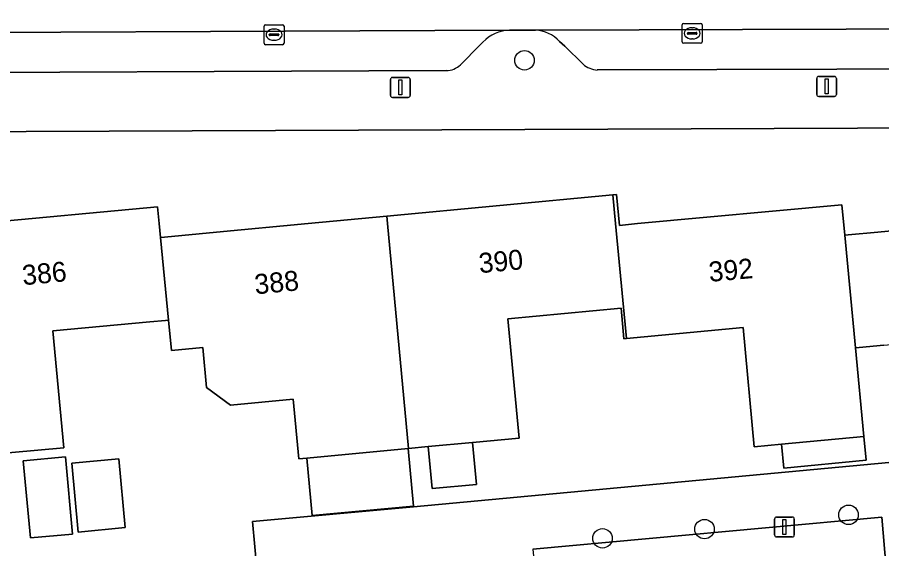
# Model space of a CAD drawing. Extents: x 157793 to 159380, y 380877 to 382313.
# Drawn here: x 158390.06 to 158433.42, y 381233.72 to 381260.34 of the extents above; entities that cross this region are included whole.
import ezdxf

# ---------------------------------------------------------------- set-up
doc = ezdxf.new("R2010")
doc.units = 0
for name, color, linetype in [('IMGEO_Boom', 7, 'Continuous'), ('IMGEO_Erf', 7, 'Continuous'), ('IMGEO_Kolk', 7, 'Continuous'), ('IMGEO_Lichtmast', 7, 'Continuous'), ('IMGEO_Muur', 7, 'Continuous'), ('IMGEO_Pand', 7, 'Continuous'), ('IMGEO_Pand_nummerreeks', 7, 'Continuous'), ('IMGEO_Parkeervlak_open', 7, 'Continuous'), ('IMGEO_Rijbaan_lokaal_gesloten', 7, 'Continuous'), ('IMGEO_Voetpad_open', 7, 'Continuous')]:
    doc.layers.add(name, color=color, linetype=linetype)

msp = doc.modelspace()

# ---------------------------------------------------------------- linework, layer by layer
at = {"layer": 'IMGEO_Boom'}
for centre in [(158415.502, 381258.182), (158431.754, 381235.411), (158424.53, 381234.699), (158419.412, 381234.236)]:
    msp.add_circle(centre, 0.489, dxfattribs=at)
at = {"layer": 'IMGEO_Erf'}
for points in [[(158457.221, 381254.886), (158373.812, 381254.547), (158374.358, 381248.767), (158385.741, 381249.78), (158388.106, 381250), (158397.101, 381250.836), (158397.182, 381250), (158397.249, 381249.305), (158397.445, 381249.323), (158400.053, 381249.568), (158404.644, 381250), (158408.591, 381250.371), (158419.936, 381251.438), (158420.115, 381251.455), (158420.259, 381249.915), (158421.175, 381250), (158431.419, 381250.951), (158431.563, 381249.427), (158431.727, 381249.442), (158433.226, 381249.581), (158437.743, 381250)], [(158433.519, 381243.917), (158432.283, 381243.801), (158432.1, 381243.784), (158432.523, 381239.343), (158432.635, 381238.147), (158428.503, 381237.758), (158428.391, 381238.954), (158427.025, 381238.826), (158426.463, 381244.799), (158420.612, 381244.249), (158420.489, 381244.237), (158420.344, 381245.77), (158414.669, 381245.236), (158415.23, 381239.262), (158412.894, 381239.042), (158413.093, 381236.936), (158410.872, 381236.727), (158410.673, 381238.833), (158409.689, 381238.741), (158409.675, 381238.74), (158409.94, 381235.854), (158404.857, 381235.386), (158404.586, 381238.26), (158404.178, 381238.222), (158403.897, 381241.207), (158400.754, 381240.911), (158399.55, 381241.787), (158399.361, 381243.795), (158397.797, 381243.648), (158397.65, 381245.17), (158397.498, 381245.156), (158396.708, 381245.082), (158391.842, 381244.624), (158392.391, 381238.778), (158388.467, 381238.425)], [(158383.543, 381226.677), (158390.701, 381227.35), (158390.56, 381228.843), (158392.511, 381229.026), (158396.772, 381229.427), (158402.322, 381229.995), (158401.867, 381235.072), (158409.933, 381235.822), (158434.485, 381238.106)]]:
    msp.add_lwpolyline(points, dxfattribs=at)
for points in [[(158392.84, 381234.453), (158390.729, 381234.255), (158390.366, 381238.119), (158392.477, 381238.318)], [(158395.48, 381234.771), (158393.124, 381234.549), (158392.8, 381237.998), (158395.156, 381238.22)]]:
    msp.add_lwpolyline(points, close=True, dxfattribs=at)
at = {"layer": 'IMGEO_Kolk'}
for p, q in [((158402.515, 381259.966), (158403.367, 381259.966)), ((158423.41, 381259.108), (158423.41, 381259.96)), ((158423.485, 381260.034), (158424.337, 381260.034)), ((158424.411, 381259.96), (158424.411, 381259.108)), ((158402.44, 381259.04), (158402.44, 381259.892)), ((158402.699, 381259.46), (158402.699, 381259.472)), ((158402.742, 381259.509), (158403.14, 381259.509)), ((158402.928, 381259.746), (158402.953, 381259.746)), ((158403.183, 381259.472), (158403.183, 381259.46)), ((158403.441, 381259.892), (158403.441, 381259.04)), ((158423.669, 381259.528), (158423.669, 381259.54)), ((158424.107, 381259.491), (158423.709, 381259.491)), ((158423.712, 381259.577), (158424.11, 381259.577)), ((158423.898, 381259.814), (158423.923, 381259.814)), ((158424.153, 381259.54), (158424.153, 381259.528)), ((158403.137, 381259.423), (158402.739, 381259.423)), ((158402.951, 381259.186), (158402.926, 381259.186)), ((158424.337, 381259.034), (158423.485, 381259.034)), ((158423.921, 381259.254), (158423.896, 381259.254)), ((158403.367, 381258.966), (158402.515, 381258.966))]:
    msp.add_line(p, q, dxfattribs=at)
for points in [[(158402.515, 381259.966), (158403.367, 381259.966)], [(158423.41, 381259.108), (158423.41, 381259.96)], [(158423.485, 381260.034), (158424.337, 381260.034)], [(158424.411, 381259.96), (158424.411, 381259.108)], [(158402.44, 381259.04), (158402.44, 381259.892)], [(158403.441, 381259.892), (158403.441, 381259.04)], [(158424.337, 381259.034), (158423.485, 381259.034)], [(158403.367, 381258.966), (158402.515, 381258.966)]]:
    msp.add_lwpolyline(points, dxfattribs=at)
for centre, radius, start, end in [((158402.517, 381259.89), 0.0765, 91.552, 178.448), ((158402.517, 381259.89), 0.0765, 91.552, 178.448), ((158403.365, 381259.89), 0.0765, 1.552, 88.448), ((158403.365, 381259.89), 0.0765, 1.552, 88.448), ((158423.487, 381259.958), 0.0765, 91.552, 178.448), ((158423.487, 381259.958), 0.0765, 91.552, 178.448), ((158424.335, 381259.958), 0.0765, 1.552, 88.448), ((158424.335, 381259.958), 0.0765, 1.552, 88.448), ((158402.739, 381259.469), 0.0403, 85.8775, 175.7526), ((158403.144, 381259.471), 0.0386, 1.7309, 96.639), ((158423.709, 381259.537), 0.0403, 85.8775, 175.7526), ((158423.706, 381259.527), 0.0366, 178.938, 274.7102), ((158424.11, 381259.534), 0.043, 264.8664, 352.4533), ((158424.114, 381259.539), 0.0386, 1.7309, 96.639), ((158402.517, 381259.042), 0.0765, 181.552, 268.448), ((158402.517, 381259.042), 0.0765, 181.552, 268.448), ((158402.736, 381259.459), 0.0366, 178.938, 274.7102), ((158403.14, 381259.466), 0.043, 264.8664, 352.4533), ((158403.365, 381259.042), 0.0765, 271.552, 358.448), ((158403.365, 381259.042), 0.0765, 271.552, 358.448), ((158423.487, 381259.11), 0.0765, 181.552, 268.448), ((158423.487, 381259.11), 0.0765, 181.552, 268.448), ((158424.335, 381259.11), 0.0765, 271.552, 358.448), ((158424.335, 381259.11), 0.0765, 271.552, 358.448)]:
    msp.add_arc(centre, radius, start, end, dxfattribs=at)
for centre, major_axis, ratio, start_param, end_param in [((158402.927, 381259.466), (-0.387, 0.002), 0.722429, 4.712389, 7.853982), ((158402.952, 381259.466), (-0.39, 0.002), 0.717154, 1.570796, 4.712389), ((158423.897, 381259.534), (-0.387, 0.002), 0.722429, 4.712389, 7.853982), ((158423.922, 381259.534), (-0.39, 0.002), 0.717154, 1.570796, 4.712389)]:
    msp.add_ellipse(centre, major_axis=major_axis, ratio=ratio, start_param=start_param, end_param=end_param, dxfattribs=at)
at = {"layer": 'IMGEO_Lichtmast'}
for p, q in [((158408.878, 381257.323), (158409.668, 381257.323)), ((158409.668, 381257.323), (158408.878, 381257.323)), ((158430.256, 381257.373), (158431.046, 381257.373)), ((158431.046, 381257.373), (158430.256, 381257.373)), ((158408.778, 381256.423), (158408.778, 381257.223)), ((158408.778, 381257.223), (158408.778, 381256.423)), ((158409.768, 381257.223), (158409.768, 381256.423)), ((158409.768, 381256.423), (158409.768, 381257.223)), ((158430.156, 381256.473), (158430.156, 381257.273)), ((158430.156, 381257.273), (158430.156, 381256.473)), ((158431.146, 381257.273), (158431.146, 381256.473)), ((158431.146, 381256.473), (158431.146, 381257.273)), ((158409.668, 381256.323), (158408.878, 381256.323)), ((158408.878, 381256.323), (158409.668, 381256.323)), ((158431.046, 381256.373), (158430.256, 381256.373)), ((158430.256, 381256.373), (158431.046, 381256.373)), ((158428.042, 381234.404), (158428.042, 381235.204)), ((158428.042, 381235.204), (158428.042, 381234.404)), ((158428.142, 381235.304), (158428.932, 381235.304)), ((158428.932, 381235.304), (158428.142, 381235.304)), ((158429.032, 381235.204), (158429.032, 381234.404)), ((158429.032, 381234.404), (158429.032, 381235.204)), ((158428.932, 381234.304), (158428.142, 381234.304)), ((158428.142, 381234.304), (158428.932, 381234.304))]:
    msp.add_line(p, q, dxfattribs=at)
for points in [[(158409.198, 381257.198), (158409.348, 381257.198), (158409.348, 381256.448), (158409.198, 381256.448), (158409.198, 381257.198)], [(158430.576, 381257.248), (158430.726, 381257.248), (158430.726, 381256.498), (158430.576, 381256.498), (158430.576, 381257.248)], [(158428.462, 381235.179), (158428.612, 381235.179), (158428.612, 381234.429), (158428.462, 381234.429), (158428.462, 381235.179)]]:
    msp.add_lwpolyline(points, dxfattribs=at)
for centre, start, end in [((158408.878, 381257.223), 90, 180), ((158408.878, 381257.223), 90, 180), ((158409.668, 381257.223), 0, 90), ((158409.668, 381257.223), 360, 90), ((158430.256, 381257.273), 90, 180), ((158430.256, 381257.273), 90, 180), ((158431.046, 381257.273), 0, 90), ((158431.046, 381257.273), 360, 90), ((158430.256, 381256.473), 180, 270), ((158430.256, 381256.473), 180, 270), ((158431.046, 381256.473), 270, 0), ((158431.046, 381256.473), 270, 0), ((158408.878, 381256.423), 180, 270), ((158408.878, 381256.423), 180, 270), ((158409.668, 381256.423), 270, 0), ((158409.668, 381256.423), 270, 0), ((158428.142, 381235.204), 90, 180), ((158428.142, 381235.204), 90, 180), ((158428.932, 381235.204), 0, 90), ((158428.932, 381235.204), 360, 90), ((158428.142, 381234.404), 180, 270), ((158428.142, 381234.404), 180, 270), ((158428.932, 381234.404), 270, 0), ((158428.932, 381234.404), 270, 0)]:
    msp.add_arc(centre, 0.1, start, end, dxfattribs=at)
at = {"layer": 'IMGEO_Muur'}
msp.add_lwpolyline([(158401.867, 381235.072), (158409.933, 381235.822)], dxfattribs=at)
at = {"layer": 'IMGEO_Pand'}
for points in [[(158414.669, 381245.236), (158420.344, 381245.77), (158420.489, 381244.237), (158420.612, 381244.249), (158420.071, 381250), (158419.936, 381251.438), (158408.591, 381250.371), (158408.626, 381250), (158409.689, 381238.741), (158410.673, 381238.833), (158412.894, 381239.042), (158415.23, 381239.262)], [(158431.563, 381249.427), (158431.419, 381250.951), (158421.175, 381250), (158420.259, 381249.915), (158420.115, 381251.455), (158419.936, 381251.438), (158420.071, 381250), (158420.612, 381244.249), (158426.463, 381244.799), (158427.025, 381238.826), (158428.391, 381238.954), (158432.523, 381239.343), (158432.1, 381243.784)], [(158397.65, 381245.17), (158397.249, 381249.305), (158397.182, 381250), (158397.101, 381250.836), (158388.106, 381250), (158385.741, 381249.78), (158386.85, 381238.28), (158388.467, 381238.425), (158392.391, 381238.778), (158391.842, 381244.624), (158396.708, 381245.082), (158397.498, 381245.156)], [(158408.626, 381250), (158408.591, 381250.371), (158404.644, 381250), (158400.053, 381249.568), (158397.445, 381249.323), (158397.249, 381249.305), (158397.65, 381245.17), (158397.797, 381243.648), (158399.361, 381243.795), (158399.55, 381241.787), (158400.754, 381240.911), (158403.897, 381241.207), (158404.178, 381238.222), (158404.586, 381238.26), (158409.675, 381238.74), (158409.689, 381238.741)], [(158442.92, 381250.48), (158437.743, 381250), (158433.226, 381249.581), (158431.727, 381249.442), (158431.563, 381249.427), (158432.1, 381243.784), (158432.283, 381243.801), (158433.519, 381243.917), (158437.958, 381244.335), (158438.38, 381239.855), (158438.492, 381238.661), (158438.513, 381238.438), (158444, 381238.93), (158442.965, 381250)], [(158432.523, 381239.343), (158428.391, 381238.954), (158428.503, 381237.758), (158432.635, 381238.147)], [(158409.675, 381238.74), (158404.586, 381238.26), (158404.857, 381235.386), (158409.94, 381235.854)], [(158412.894, 381239.042), (158410.673, 381238.833), (158410.872, 381236.727), (158413.093, 381236.936)], [(158390.366, 381238.119), (158390.729, 381234.255), (158392.84, 381234.453), (158392.477, 381238.318)], [(158392.8, 381237.998), (158393.124, 381234.549), (158395.48, 381234.771), (158395.156, 381238.22)]]:
    msp.add_lwpolyline(points, close=True, dxfattribs=at)
at = {"layer": 'IMGEO_Parkeervlak_open'}
for points in [[(158414.748, 381259.693), (158377.232, 381259.519)], [(158452.413, 381259.816), (158416.045, 381259.7)], [(158413.256, 381258.94), (158413.419, 381259.093)], [(158417.259, 381259.125), (158417.518, 381258.886), (158418.442, 381257.987)], [(158412.287, 381257.955), (158413.256, 381258.94)], [(158419.153, 381257.698), (158449.192, 381257.786)], [(158380.538, 381257.539), (158411.576, 381257.67)]]:
    msp.add_lwpolyline(points, dxfattribs=at)
msp.add_lwpolyline([(158434.025, 381229.887), (158433.976, 381230.217), (158433.857, 381230.192), (158433.421, 381235.303), (158415.915, 381233.688), (158416.46, 381228.231)], close=True, dxfattribs=at)
for centre, radius, start, end in [((158414.809, 381257.786), 1.908, 91.8329, 136.7624), ((158415.951, 381257.933), 1.77, 42.353, 86.9587), ((158411.576, 381258.701), 1.031, 270.0257, 313.6605), ((158419.21, 381258.857), 1.161, 228.5733, 267.1862)]:
    msp.add_arc(centre, radius, start, end, dxfattribs=at)
at = {"layer": 'IMGEO_Rijbaan_lokaal_gesloten'}
msp.add_lwpolyline([(158414.748, 381259.693), (158415.841, 381259.699), (158416.045, 381259.7), (158452.413, 381259.816), (158453.527, 381259.813), (158453.494, 381265.863), (158447.459, 381265.784), (158394.254, 381265.587), (158381.644, 381265.541), (158374.137, 381265.491), (158374.097, 381259.557), (158375.117, 381259.544), (158377.232, 381259.519)], close=True, dxfattribs=at)
at = {"layer": 'IMGEO_Voetpad_open'}
for points in [[(158416.045, 381259.7), (158415.841, 381259.699), (158414.748, 381259.693)], [(158413.419, 381259.093), (158413.256, 381258.94), (158412.287, 381257.955)], [(158418.442, 381257.987), (158417.518, 381258.886), (158417.259, 381259.125)], [(158449.192, 381257.786), (158419.153, 381257.698)], [(158411.576, 381257.67), (158380.538, 381257.539)], [(158369.385, 381254.529), (158373.812, 381254.547), (158457.221, 381254.886), (158459.094, 381254.91)], [(158415.915, 381233.688), (158433.421, 381235.303), (158433.857, 381230.192), (158433.976, 381230.217), (158435.253, 381230.392), (158434.485, 381238.106), (158409.933, 381235.822), (158401.867, 381235.072), (158402.322, 381229.995), (158403.446, 381218.363), (158403.568, 381216.879), (158417.373, 381217.577), (158416.824, 381223.289), (158415.796, 381223.213)]]:
    msp.add_lwpolyline(points, dxfattribs=at)
for centre, radius, start, end in [((158414.809, 381257.786), 1.908, 91.8329, 136.7624), ((158415.951, 381257.933), 1.77, 42.353, 86.9587), ((158411.576, 381258.701), 1.031, 270.0257, 313.6605), ((158419.21, 381258.857), 1.161, 228.5733, 267.1862)]:
    msp.add_arc(centre, radius, start, end, dxfattribs=at)

# ---------------------------------------------------------------- texts
at = {"layer": 'IMGEO_Pand_nummerreeks'}
for s, rotation, p in [('390', 5.3743, (158413.251, 381247.515)), ('392', 4.9618, (158424.779, 381247.083)), ('386', 5.3113, (158390.353, 381246.914)), ('388', 5.3743, (158402.005, 381246.457))]:
    msp.add_text(s, height=1, rotation=rotation, dxfattribs=at).set_placement(p)

doc.saveas('drawing.dxf')
